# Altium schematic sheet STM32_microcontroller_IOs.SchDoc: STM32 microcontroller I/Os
size A4; Author: Ph.A; SheetNumber: 3; SheetTotal: 8
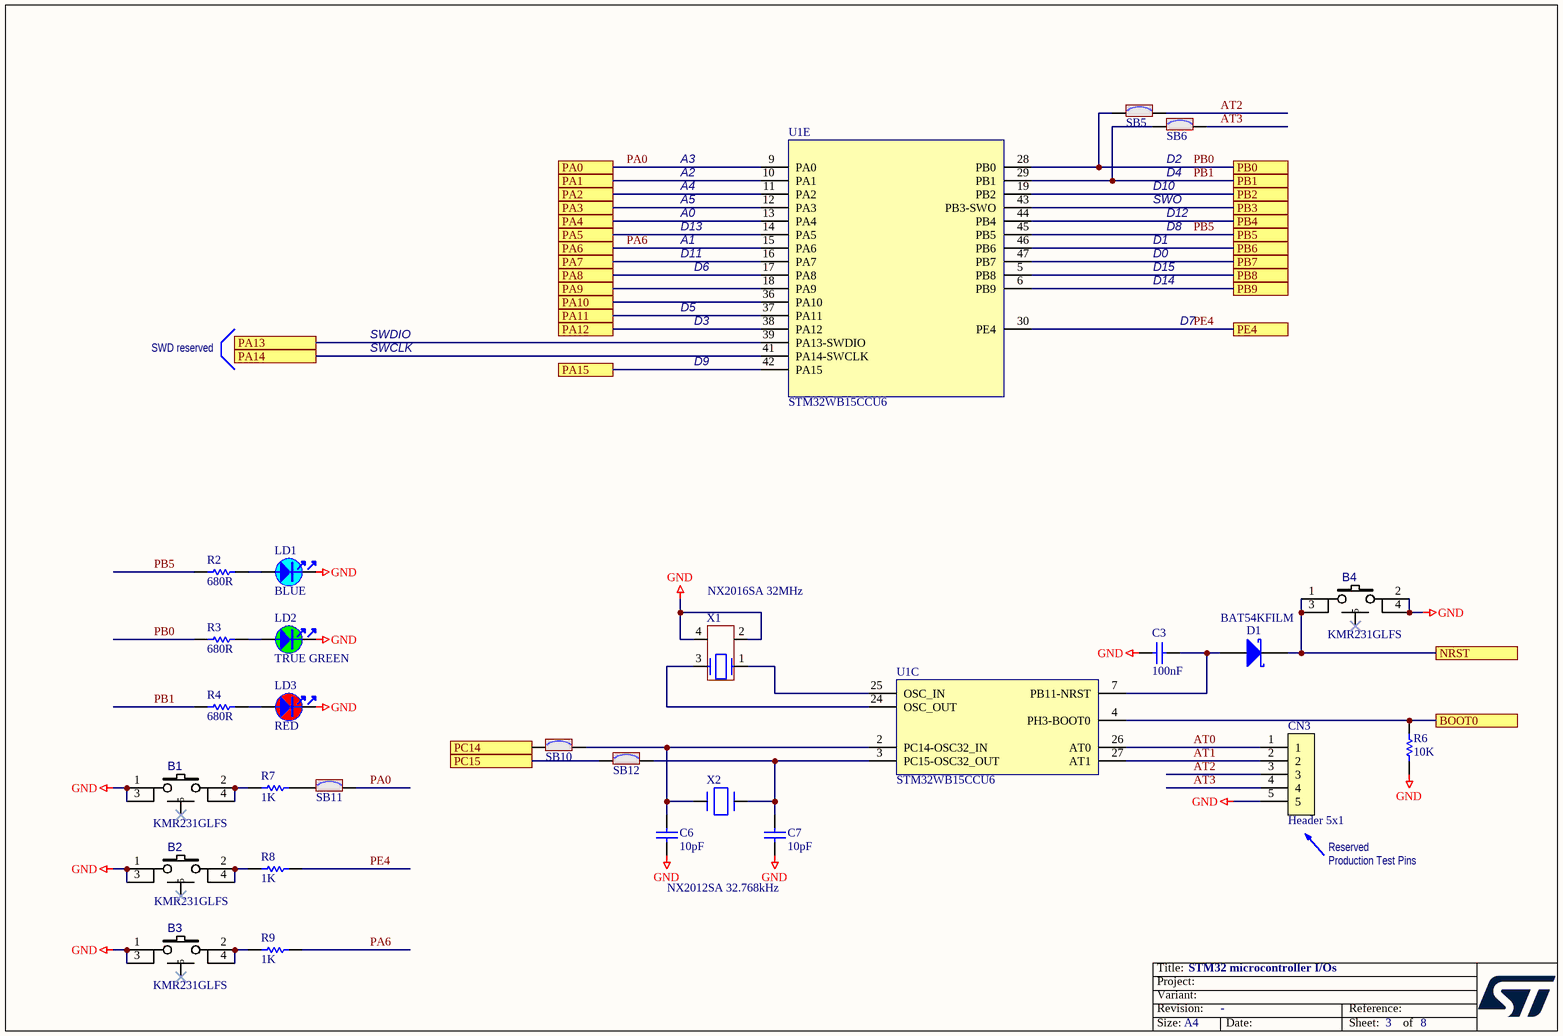
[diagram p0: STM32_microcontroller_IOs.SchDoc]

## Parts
B1  value KMR231GLFS  [SWI_C&K_Y78B23110FP__ITT_KMR231GLFS]  (hidden comment: SW-PUSH-CMS_KMR2_BLACK)
B2  value KMR231GLFS  [SWI_C&K_Y78B23110FP__ITT_KMR231GLFS]  (hidden comment: SW-PUSH-CMS_KMR2_BLACK)
B3  value KMR231GLFS  [SWI_C&K_Y78B23110FP__ITT_KMR231GLFS]  (hidden comment: SW-PUSH-CMS_KMR2_BLACK)
B4  value KMR231GLFS  [SWI_C&K_Y78B23110FP__ITT_KMR231GLFS]  (hidden comment: SW-PUSH-CMS_KMR2_BLACK)
C3  value 100nF  [C0402]  (hidden comment: Capacitor)
C6  value 10pF  [C0402]  (hidden comment: Capacitor)
C7  value 10pF  [C0402]  (hidden comment: Capacitor)
CN3  Header 5x1  [CON_SAMTEC_TSW-105-07-X-S]
D1  value BAT54KFILM  [DIO_SOD523_1A_2K]  (hidden comment: SCHOTTKY_1A_2K)
LD1  value BLUE  [LED_0603_VISHAY_VLMB1300-GS08_BLUE_1A2K_H0P8]  (hidden comment: LED_blue)
LD2  value TRUE GREEN  [LED_0603_VISHAY_VLMTG1300-GS08_GREEN_1A2K_H0P8]  (hidden comment: LED_green)
LD3  value RED  [LED_0603_VISHAY_VLMS1300-GS08_RED_1A2K_H0P8]  (hidden comment: LED_red)
R2  value 680R  [R0402]  (hidden comment: Resistor)
R3  value 680R  [R0402]  (hidden comment: Resistor)
R4  value 680R  [R0402]  (hidden comment: Resistor)
R6  value 10K  [R0402]  (hidden comment: Resistor)
R7  value 1K  [R0402]  (hidden comment: Resistor)
R8  value 1K  [R0402]  (hidden comment: Resistor)
R9  value 1K  [R0402]  (hidden comment: Resistor)
SB5  SB_ON  [SOLDER-BRIDGE_R0402-0R]  (value not drawn)
SB6  SB_ON  [SOLDER-BRIDGE_R0402-0R]  (value not drawn)
SB10  SB_ON  [SOLDER-BRIDGE_R0402-0R]  (value not drawn)
SB11  SB_ON  [SOLDER-BRIDGE_R0402-0R]  (value not drawn)
SB12  SB_ON  [SOLDER-BRIDGE_R0402-0R]  (value not drawn)
U1  value STM32WB15CCU6  [ICC_UFQFPN48-EPAD_7X7_H0P55_P050]  (hidden comment: STM32WB15_QFN48)  (parts C,E of 5)
X1  value NX2016SA 32MHz  [CRY_NX2016SA_4P]  (hidden comment: XTAL_4_PINS)
X2  value NX2012SA 32.768kHz  [CRY_NX2012SA_2P]  (hidden comment: XTAL_2_PINS)

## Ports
BOOT0, NRST, PA0, PA1, PA2, PA3, PA4, PA5, PA6, PA7, PA8, PA9, PA10, PA11, PA12, PA13, PA14, PA15, PB0, PB1, PB2, PB3, PB4, PB5, PB6, PB7, PB8, PB9, PC14, PC15, PE4

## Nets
GND: B1.1 B1.3 B2.1 B2.3 B3.1 B3.3 B4.2 B4.4 C3.1 C6.1 C7.1 CN3.5 LD1.2 LD2.2 LD3.2 R6.1 X1.2 X1.4
AT0: CN3.1 U1.26(AT0)
AT1: CN3.2 U1.27(AT1)
AT2: CN3.3 SB5.2
AT3: CN3.4 SB6.2
BOOT0: R6.2 U1.4(PH3-BOOT0) ; port BOOT0
NRST: B4.1 B4.3 D1.2(K) ; port NRST
PA0: SB11.2 U1.9(PA0) ; port PA0
PA1: U1.10(PA1) ; port PA1
PA2: U1.11(PA2) ; port PA2
PA3: U1.12(PA3) ; port PA3
PA4: U1.13(PA4) ; port PA4
PA5: U1.14(PA5) ; port PA5
PA6: R9.2 U1.15(PA6) ; port PA6
PA7: U1.16(PA7) ; port PA7
PA8: U1.17(PA8) ; port PA8
PA9: U1.18(PA9) ; port PA9
PA10: U1.36(PA10) ; port PA10
PA11: U1.37(PA11) ; port PA11
PA12: U1.38(PA12) ; port PA12
PA13: U1.39(PA13-SWDIO) ; port PA13
PA14: U1.41(PA14-SWCLK) ; port PA14
PA15: U1.42(PA15) ; port PA15
PB0: R3.1 SB5.1 U1.28(PB0) ; port PB0
PB1: R4.1 SB6.1 U1.29(PB1) ; port PB1
PB2: U1.19(PB2) ; port PB2
PB3: U1.43(PB3-SWO) ; port PB3
PB4: U1.44(PB4) ; port PB4
PB5: R2.1 U1.45(PB5) ; port PB5
PB6: U1.46(PB6) ; port PB6
PB7: U1.47(PB7) ; port PB7
PB8: U1.5(PB8) ; port PB8
PB9: U1.6(PB9) ; port PB9
PC14: SB10.1 ; port PC14
PC15: SB12.1 ; port PC15
PE4: R8.2 U1.30(PE4) ; port PE4
NetB1_2: B1.2 B1.4 R7.1
NetB2_2: B2.2 B2.4 R8.1
NetB3_2: B3.2 B3.4 R9.1
NetC3_2: C3.2 D1.1(A) U1.7(PB11-NRST)
NetC6_2: C6.2 SB10.2 U1.2(PC14-OSC32_IN) X2.1(X1)
NetC7_2: C7.2 SB12.2 U1.3(PC15-OSC32_OUT) X2.2(X2)
NetLD1_1: LD1.1 R2.2
NetLD2_1: LD2.1 R3.2
NetLD3_1: LD3.1 R4.2
NetR7_2: R7.2 SB11.1
NetU1_24: U1.24(OSC_OUT) X1.3
NetU1_25: U1.25(OSC_IN) X1.1

Not connected (* = marked no-connect by the designer): B1 5*; B2 5*; B3 5*; B4 5*

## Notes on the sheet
- A2
- A3
- D2
- D4
- D13
- A4
- A5
- A0
- A1
- D1
- SWO
- D10
- D12
- D8
- D5
- D11
- D6
- D0
- D14
- D15
- SWD reserved
- SWDIO
- SWCLK
- D9
- D3
- D7
- Reserved
- Production Test Pins

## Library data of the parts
B1-B4 = MCD-01485: Microminiature Tact Switch for SMT - KMR 2 Series - 1.9 mm height; Part_Type: Misc; Manufacturer: C&K; Part_Preference: Recommended
C3 = MCD-00006: Capacitor, MLCC, 100nF, 16V, X7R, +/-10%, 0402, T=0.5mm; Manufacturer_Part_Number: CC0402KRX7R7BB104; Manufacturer: YAGEO; Alternate_Manufacturer_Part_Number: GCM155R71C104KA55D; Alternate_Manufacturer: MURATA; Part_Preference: Recommended; Order_Code_RS: 616-9701
C6 C7 = MCD-00015: Capacitor, MLCC, 10pF, 50V, NPO, +/-5%, 0402, T=0,5mm; Manufacturer_Part_Number: CC0402JRNPO9BN100; Manufacturer: YAGEO; Part_Preference: Recommended
CN3 = MCD-02060: Header, 5x1, 2,54mm, VR, TH, Height 5.84mm/2.54mm; Part_Type: Connector; Manufacturer_Part_Number: TSW-105-07-G-S; Manufacturer: SAMTEC; Part_Preference: Recommended; Order_Code_RS: 161-2268
D1 = MCD-01677: Small signal Schottky diodes; Part_Type: Diode; Manufacturer: STMICROELECTRONICS; BMS_Part_Number: 9151123; Part_Preference: Recommended; Manufacturer_HQ_COO: EU
LD1 = MCD-00584: LED Blue, 0603 SMD, 3.3 V Forward Voltage; Part_Type: Display; Manufacturer_Part_Number: VLMB1300-GS08; Manufacturer: VISHAY; Part_Preference: Recommended; Order_Code_RS: 7730430
LD2 = MCD-00589: LED Green, 0603 SMD, Fw Voltage = 2.8V - 3.6V; Part_Type: Display; Manufacturer_Part_Number: VLMTG1300-GS08; Manufacturer: VISHAY; Alternate_Manufacturer_Part_Number: LG Q396-PS-35; Alternate_Manufacturer: OSRAM OPTO SEMICONDUCTORS; Part_Preference: Recommended; Order_Code_RS: 7730452
LD3 = MCD-00587: LED Red, 0603 SMD, 2V Forward Voltage; Part_Type: Display; Manufacturer_Part_Number: VLMS1300-GS08; Manufacturer: VISHAY; Alternate_Manufacturer_Part_Number: LS Q976-NR-1; Alternate_Manufacturer: OSRAM OPTO SEMICONDUCTORS; Part_Preference: Recommended
R2-R4 = MCD-00507: Resistor,680R,0402,1%,1/16W; Manufacturer_Part_Number: RC0402FR-07680RL; Manufacturer: YAGEO; Part_Preference: Recommended
R6 = MCD-00053: Resistor,10K,0402,1%,1/16W; Manufacturer_Part_Number: RC0402FR-0710KL; Manufacturer: YAGEO; BMS_Part_Number: 9131590; Part_Preference: Recommended
R7-R9 = MCD-00061: Resistor,1K,0402,1%,1/16W; Manufacturer_Part_Number: RC0402FR-071KL; Manufacturer: YAGEO; Part_Preference: Recommended
SB5 SB6 SB10-SB12 = MCD-01618: Solder Bridge 0402 ON; Part_Type: Misc; Manufacturer_Part_Number: RC0402JR-070RL; Manufacturer: YAGEO; Part_Preference: Recommended; Order_Code_RS: 618-5804
U1 = MCD-02058: Multiprotocol wireless 32-bit MCU ARM®-based Cortex®-M4 with FPU, Bluetooth® Low-Energy and 802.15.4 radio solution; Part_Type: IC; Manufacturer: STMICROELECTRONICS; Part_Preference: Recommended; Manufacturer_HQ_COO: EU; Component_Country_Of_Origin: China
X1 = MCD-01446: Crystal 32MHz, 8pF, +-10ppm, 60ohms max, SMD; Part_Type: Crystal oscillator; Manufacturer_Part_Number: NX2016SA 32MHz EXS00A-CS06654; Manufacturer: NDK; BMS_Part_Number: 9157042; Part_Preference: Recommended
X2 = MCD-01445: Crystal 32.768kHz, 7pF, +-20ppm, 80Kohms max, SMD; Part_Type: Crystal oscillator; Manufacturer_Part_Number: NX2012SA 32.768kHz EXS00A-MU00389; Manufacturer: NDK; BMS_Part_Number: 9157043; Part_Preference: Recommended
